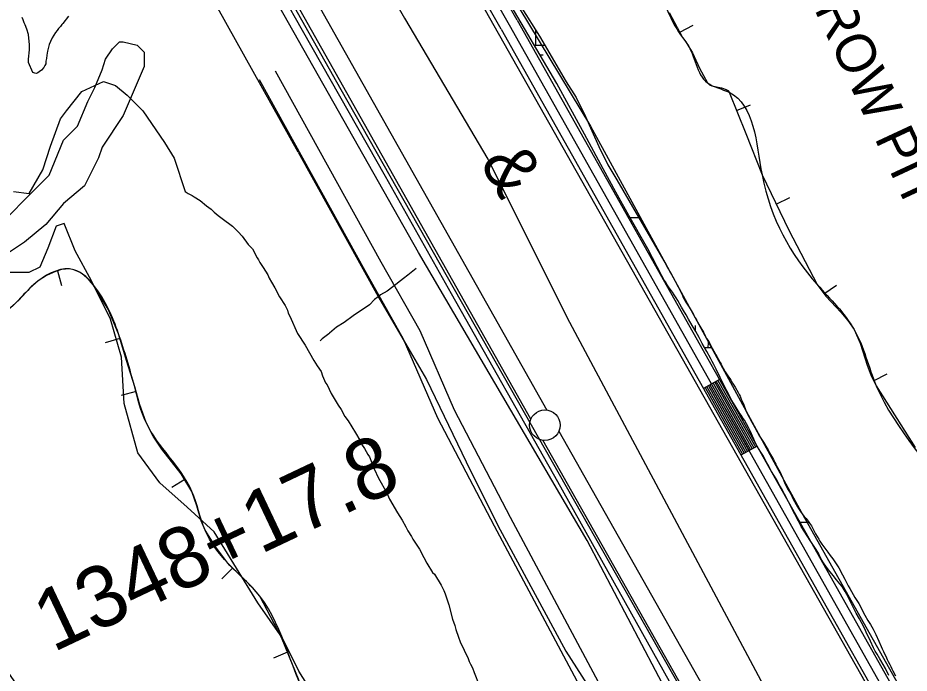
# Model space of a CAD drawing. Extents: x 3177185 to 3215018, y 812988 to 838321.
# Drawn here: x 3193125 to 3194584, y 822130 to 823203 of the extents above; entities that cross this region are included whole.
import ezdxf

# ---------------------------------------------------------------- set-up
doc = ezdxf.new("R2010")
doc.units = 0
for name, color, linetype in [('V-BORW-IDEN', 7, 'Continuous'), ('V-BORW-LINE', 7, 'Continuous'), ('V-LEVE-TOET', 7, 'Continuous'), ('V-RAIL-IDEN', 7, 'Continuous'), ('V-RAIL-TRAK', 7, 'Continuous'), ('V-ROAD-CNTR', 7, 'Continuous'), ('V-SITE-VEGE', 7, 'Continuous'), ('V-SURV-IDEN', 7, 'Continuous'), ('V-SURV-LINE', 7, 'Continuous'), ('V-TOPO-SHOR', 7, 'Continuous'), ('V-WETL-SWMP', 7, 'Continuous')]:
    doc.layers.add(name, color=color, linetype=linetype)

msp = doc.modelspace()

# ---------------------------------------------------------------- linework, layer by layer
at = {"layer": 'V-BORW-LINE'}
for p, q in [((3194208.7, 823179.2), (3194230.8, 823191)), ((3194301.5, 823051.1), (3194324.6, 823060.5)), ((3194366.5, 822897.8), (3194389, 822908.7)), ((3193190.1, 822788.7), (3193197.1, 822764.7)), ((3194444.7, 822750.9), (3194465.1, 822765.5)), ((3193292.5, 822678.2), (3193268.6, 822671)), ((3194526, 822608.6), (3194548.3, 822620)), ((3193318.9, 822591.2), (3193294.8, 822584.6)), ((3193398.5, 822446.9), (3193377.2, 822433.8)), ((3193477, 822302.2), (3193459.5, 822284.4)), ((3193566.8, 822164.2), (3193543.6, 822154.7))]:
    msp.add_line(p, q, dxfattribs=at)
for points in [[(3194191.4, 823211.7), (3194213.4, 823170.5), (3194216.8, 823165.7), (3194220.4, 823161), (3194229.5, 823145.4), (3194241, 823120.5), (3194253.9, 823096.6), (3194257.2, 823093.3), (3194261, 823091.5), (3194277.1, 823088.2), (3194284.4, 823085.8), (3194287.2, 823083.8), (3194289.3, 823081), (3194316.7, 823013.5), (3194343.3, 822945.9), (3194387, 822855.3), (3194433.8, 822766.2), (3194447.6, 822747), (3194472.2, 822720.8), (3194483.9, 822707.4), (3194494, 822692.8), (3194504.1, 822670.2), (3194515.4, 822634.3), (3194521.8, 822616.7), (3194530.3, 822600.2), (3194593.9, 822499.3)], [(3193316.9, 822598.6), (3193303.4, 822642.1), (3193290.2, 822685.8), (3193273, 822726.2), (3193249.5, 822765), (3193242.6, 822773.6), (3193236.8, 822779.3), (3193227.3, 822786.2), (3193217.2, 822790.6), (3193210.2, 822791.8), (3193197.1, 822790.7), (3193187.1, 822787.8), (3193172.2, 822780.9), (3193158.6, 822772.1), (3193145, 822760.2), (3193126.8, 822740.6), (3193107.6, 822723.1)], [(3193585.9, 822117.5), (3193556.8, 822188.5), (3193521.5, 822255.9), (3193509.5, 822270.3), (3193469.1, 822310), (3193449.3, 822336.3), (3193431.9, 822364.3), (3193425.4, 822379.7), (3193418.6, 822404.1), (3193410.3, 822427.7), (3193392.6, 822456.4), (3193361.3, 822497), (3193346.8, 822518), (3193335.2, 822540.6), (3193324.9, 822569.2), (3193316.9, 822598.6)]]:
    msp.add_lwpolyline(points, dxfattribs=at)
for points in [[(3194173.2, 823254.5), (3194133.8, 823323.1), (3194017.5, 823523.4), (3193991.8, 823555.6), (3193946.2, 823648.6), (3193888.3, 823652.4), (3193891.4, 823658.1), (3193914.7, 823669.6), (3193993, 823701.8), (3194039.3, 823727.5), (3194160.2, 823798.2), (3194326.1, 823907.6), (3194436.7, 823987.3), (3194502.9, 824036.7), (3194535.5, 824045.1), (3194547.6, 824055.8), (3194568.2, 824150.6), (3194657.5, 824394.2), (3194690.3, 824441.2), (3194711.1, 824446.4), (3194734.7, 824446.4), (3194770.2, 824392.5), (3194839.9, 824358.9), (3194843.7, 824354.2), (3194822.9, 824352.6), (3194805.6, 824354.5), (3194783.8, 824344), (3194808, 824310.6), (3194860.9, 824111.5), (3194890.3, 824049), (3194919.9, 824022.8), (3194936.8, 823993.7), (3194967.5, 823945.1), (3194990.2, 823878.8), (3195044.4, 823786.8), (3195063.9, 823718), (3195053.2, 823688.8), (3195056.3, 823616.2), (3195008.6, 823396.2), (3194962.2, 823257.3), (3194949.6, 823254.7), (3194916.1, 823270.5), (3194892.6, 823394.4), (3194818.7, 823675.4), (3194764.8, 823725), (3194732.1, 823768.5), (3194627.7, 823861.2), (3194598.2, 823922.8), (3194572.9, 824011.1), (3194544.8, 824024.5), (3194532.2, 824018.4), (3194535.7, 823972.4), (3194544.3, 823935.6), (3194590.6, 823765.3), (3194640.4, 823657.8), (3194680.8, 823529.9), (3194719.1, 823459), (3194750.6, 823333.9), (3194793.9, 823142.5), (3194772.9, 823135.8), (3194752.4, 823099.7), (3194748.5, 823050.4), (3194776.1, 822932.3), (3194811.1, 822874.8), (3194830.8, 822797.1), (3194831.1, 822768.9), (3194796.7, 822656), (3194757.4, 822452), (3194745.4, 822448.1), (3194718.1, 822363.5), (3194698.9, 822349.8), (3194685.3, 822355.9), (3194657.8, 822398.5), (3194530.3, 822600.2), (3194494, 822692.8), (3194433.8, 822766.2), (3194343.3, 822945.9), (3194289.3, 823081), (3194253.9, 823096.6), (3194220.4, 823161), (3194213.4, 823170.5), (3194173.2, 823254.5)], [(3193316.9, 822598.6), (3193335.2, 822540.6), (3193410.3, 822427.7), (3193431.9, 822364.3), (3193469.1, 822310), (3193521.5, 822255.9), (3193609.2, 822072.6), (3193646.8, 822019.2), (3193676.9, 821957.1), (3193720.8, 821903.1), (3193750, 821838.8), (3193830.2, 821730.3), (3193879.7, 821614.9), (3193980.5, 821434.8), (3194001.3, 821375.3), (3194045.6, 821322.9), (3194255.4, 820971.9), (3194278.3, 820910.6), (3194299.8, 820853), (3194335.6, 820798.4), (3194443.8, 820680.4), (3194483.4, 820494.4), (3194474.8, 820430), (3194362.4, 820338.7), (3194243.4, 820273.7), (3194115.5, 820232.8), (3193985.1, 820192.2), (3193871, 820096.9), (3193700.8, 819982), (3193642.2, 819950.8), (3193574.5, 819997.4), (3193482.7, 820109.4), (3193411.4, 820226.4), (3193461, 820288.3), (3193516, 820325.3), (3193569.4, 820370.5), (3193689.7, 820437.3), (3193809.3, 820477.2), (3193921.8, 820552.8), (3193973.7, 820602), (3193968.2, 820665.5), (3193943.7, 820740.3), (3193889.6, 820861.5), (3193818.7, 820974.4), (3193871.9, 821026.9), (3193893.2, 821093.5), (3193831.6, 821288.3), (3193762, 821415.9), (3193682.1, 821525.7), (3193580.7, 821633.2), (3193582.1, 821571.4), (3193675.7, 821399.4), (3193689.4, 821337.7), (3193683, 821270), (3193666, 821201.1), (3193594.8, 821238.9), (3193552.5, 821298.8), (3193499, 821351.2), (3193535.6, 821424), (3193485.3, 821613.1), (3193426.4, 821662.5), (3193356.9, 821777.8), (3193308.4, 821900.5), (3193294.3, 821963), (3193279.7, 822022.1), (3193265.1, 822081.6), (3193249.6, 822013.9), (3193262.2, 821951.7), (3193210.3, 822002.4), (3193038.4, 822236.4), (3192901.1, 822477.4), (3192892.6, 822538.2), (3192940.3, 822603.2), (3192988.9, 822662), (3193107.6, 822723.1), (3193158.6, 822772.1), (3193217.2, 822790.6), (3193249.5, 822765), (3193290.2, 822685.8), (3193316.9, 822598.6)]]:
    msp.add_spline(points, degree=3, dxfattribs=at)
at = {"layer": 'V-LEVE-TOET'}
for points in [[(3193506.6, 823644.9), (3193758.4, 823202.4), (3193894.5, 822971.4)], [(3193584.3, 822982.9), (3193407.8, 823299.3)], [(3193584.3, 822982.9), (3193715.2, 822746.5), (3193715.3, 822746.3)], [(3193894.5, 822971.4), (3194028.2, 822704.5), (3194448.5, 821917.6)], [(3193715.3, 822746.3), (3193717.9, 822741.8), (3193794.1, 822610.8), (3193858.9, 822476), (3193911.1, 822371.7), (3194022.5, 822165.9), (3194144.7, 821975), (3194195.9, 821891.8), (3194255.3, 821803.4)]]:
    msp.add_lwpolyline(points, dxfattribs=at)
at = {"layer": 'V-RAIL-TRAK'}
for points in [[(3193727.3, 822943), (3193577.7, 823206), (3193415.9, 823494.6), (3193219.9, 823842.7), (3193027.5, 824182.9), (3192797.1, 824592.3), (3192558.2, 825016.7), (3192352.2, 825381.7), (3192184.3, 825679.9), (3191974.4, 826050.6), (3191871.7, 826233.9)], [(3194238.4, 822033.7), (3194009.1, 822443.2), (3193835.4, 822751.2), (3193727.3, 822943)]]:
    msp.add_lwpolyline(points, dxfattribs=at)
at = {"layer": 'V-ROAD-CNTR'}
for p, q in [((3194273.8, 822610.8), (3194247.6, 822596)), ((3194335.1, 822501.8), (3194308.9, 822487.1))]:
    msp.add_line(p, q, dxfattribs=at)
for points in [[(3193916.6, 823184.2), (3193721.8, 823525.6), (3193306.3, 824253.5), (3192602.8, 825503.8), (3192579.7, 825544.8), (3192573, 825567.5), (3192571, 825597.1), (3192577.3, 825631.2), (3192615.1, 825721.3), (3192625.4, 825758.7), (3192631.4, 825785.7), (3192630.5, 825811.3), (3192625.4, 825832.9), (3192604.1, 825875.3), (3192381.8, 826278.2), (3192358.9, 826315.5), (3192335.4, 826340.9), (3192319.5, 826354.7), (3192289.4, 826371.6), (3192167.7, 826420.9)], [(3191892.3, 826207.1), (3193654.2, 823085.5)], [(3193942.6, 823199), (3193747.9, 823540.4), (3193728, 823575.3)], [(3193734.8, 823533), (3193929.6, 823191.6)], [(3193942.7, 823199), (3195097.4, 821147.5)], [(3193916.5, 823184.3), (3195071.3, 821132.7)], [(3193929.6, 823191.6), (3195084.4, 821140.1)], [(3193546.7, 823116.4), (3193719.6, 822803.7), (3193783.2, 822690.8), (3193839.5, 822561.1), (3193931.2, 822385.2), (3194075.1, 822116.1), (3194127.2, 822033.7), (3194185.2, 821977.8), (3194639.7, 821147.1), (3195029.5, 820446.4), (3195072.9, 820348.7), (3195192.1, 820158.7), (3195238.4, 820041.1), (3195343.7, 819857.8), (3195584.5, 819427.5), (3195690.6, 819249.8), (3195813.3, 819032.3), (3196001.4, 818698.6), (3196174.6, 818374.5)], [(3193520.4, 823101.8), (3193693.4, 822789.1), (3193756.3, 822677.4), (3193812.4, 822548.2), (3193904.7, 822371.2), (3194049.2, 822101), (3194103.8, 822014.6), (3194161.1, 821959.4), (3194613.5, 821132.6), (3195002.6, 820433), (3195046.3, 820334.6), (3195165.2, 820145.1), (3195211.3, 820028), (3195317.6, 819843), (3195558.5, 819412.5), (3195664.6, 819234.7), (3195787.2, 819017.6), (3195975.1, 818684.1), (3196148.1, 818360.4)], [(3193654.2, 823085.5), (3194393.6, 821781.9), (3194932.5, 820818.5), (3195643.8, 819559.4), (3196039.6, 818863.6), (3196103.7, 818747.1), (3196200.1, 818577.4), (3196283.3, 818430.9), (3196319.7, 818367.1)], [(3194271.1, 822609.3), (3194332.5, 822500.4)], [(3194250.2, 822597.5), (3194311.5, 822488.6)], [(3194252.8, 822599), (3194314.2, 822490.1)], [(3194255.5, 822600.5), (3194316.8, 822491.5)], [(3194258.1, 822601.9), (3194319.4, 822493)], [(3194260.7, 822603.4), (3194322, 822494.5)], [(3194263.3, 822604.9), (3194324.6, 822495.9)], [(3194265.9, 822606.3), (3194327.2, 822497.4)], [(3194268.5, 822607.8), (3194329.8, 822498.9)]]:
    msp.add_lwpolyline(points, dxfattribs=at)
at = {"layer": 'V-SITE-VEGE'}
for p, q in [((3193230.4, 823082.5), (3193265.7, 823098.5)), ((3193265.7, 823098.5), (3193285, 823092.1)), ((3193285, 823092.1), (3193304.3, 823076.1)), ((3193204.8, 823050.4), (3193230.4, 823082.5)), ((3193304.3, 823076.1), (3193329.9, 823050.4)), ((3193195.1, 823037.5), (3193204.8, 823050.4)), ((3193329.9, 823050.4), (3193365.2, 822999)), ((3193179.1, 822992.6), (3193195.1, 823037.5)), ((3193166.3, 822954.1), (3193179.1, 822992.6)), ((3193365.2, 822999), (3193381.3, 822973.3)), ((3193381.3, 822973.3), (3193399, 822918.7)), ((3193143.8, 822915.5), (3193166.3, 822954.1)), ((3193118.1, 822918.7), (3193143.8, 822915.5)), ((3193399, 822918.7), (3193404.4, 822915.5)), ((3193404.4, 822915.5), (3193410.7, 822912.2)), ((3193410.7, 822912.2), (3193413.8, 822909.8)), ((3193413.8, 822909.8), (3193423.9, 822904.1)), ((3193423.9, 822904.1), (3193434, 822895.2)), ((3193434, 822895.2), (3193441.8, 822889.6)), ((3193441.8, 822889.6), (3193446.5, 822884.8)), ((3193446.5, 822884.8), (3193453.5, 822879.1)), ((3193453.5, 822879.1), (3193459.7, 822874.3)), ((3193459.7, 822874.3), (3193476.8, 822862.1)), ((3193188, 822861.7), (3193174.6, 822826)), ((3193201.4, 822866.2), (3193188, 822861.7)), ((3193219.3, 822821.5), (3193201.4, 822866.2)), ((3193476.8, 822862.1), (3193486.1, 822852.5)), ((3193486.1, 822852.5), (3193492.3, 822845.3)), ((3193492.3, 822845.3), (3193502.3, 822831.7)), ((3193502.3, 822831.7), (3193509.3, 822824.5)), ((3193174.6, 822826), (3193161.2, 822794.7)), ((3193246.1, 822772.4), (3193219.3, 822821.5)), ((3193509.3, 822824.5), (3193516.9, 822810.1)), ((3193516.9, 822810.1), (3193519.2, 822806.9)), ((3193519.2, 822806.9), (3193521.5, 822802.2)), ((3193521.5, 822802.2), (3193526.9, 822794.2)), ((3193143.4, 822785.8), (3193107.6, 822785.8)), ((3193161.2, 822794.7), (3193143.4, 822785.8)), ((3193526.9, 822794.2), (3193534.5, 822782.2)), ((3193277.3, 822709.8), (3193246.1, 822772.4)), ((3193534.5, 822782.2), (3193536.8, 822776.7)), ((3193536.8, 822776.7), (3193540.6, 822770.3)), ((3193540.6, 822770.3), (3193546, 822760.7)), ((3193546, 822760.7), (3193553.6, 822746.4)), ((3193553.6, 822746.4), (3193562.8, 822732)), ((3193562.8, 822732), (3193566.6, 822724.1)), ((3193566.6, 822724.1), (3193568.1, 822719.3)), ((3193568.1, 822719.3), (3193570.4, 822714.5)), ((3193570.4, 822714.5), (3193583.3, 822685.9)), ((3193295.2, 822647.3), (3193277.3, 822709.8)), ((3193583.3, 822685.9), (3193595.6, 822666.8)), ((3193595.6, 822666.8), (3193610.1, 822642.1)), ((3193299.6, 822571.3), (3193295.2, 822647.3)), ((3193610.1, 822642.1), (3193615.5, 822633.3)), ((3193615.5, 822633.3), (3193621.6, 822623.7)), ((3193621.6, 822623.7), (3193623.9, 822616.6)), ((3193623.9, 822616.6), (3193629.2, 822605.5)), ((3193629.2, 822605.5), (3193631.5, 822602.3)), ((3193631.5, 822602.3), (3193638.3, 822587.9)), ((3193638.3, 822587.9), (3193649.8, 822568.8)), ((3193322, 822490.9), (3193299.6, 822571.3)), ((3193649.8, 822568.8), (3193654.4, 822561.6)), ((3193654.4, 822561.6), (3193660.5, 822550.5)), ((3193660.5, 822550.5), (3193665.9, 822543.3)), ((3193665.9, 822543.3), (3193678.2, 822523.3)), ((3193678.2, 822523.3), (3193685.1, 822511.4)), ((3193685.1, 822511.4), (3193688.1, 822505)), ((3193688.1, 822505), (3193692.7, 822497.8)), ((3193692.7, 822497.8), (3193698.1, 822488.3)), ((3193357.7, 822441.8), (3193322, 822490.9)), ((3193698.1, 822488.3), (3193701.1, 822484.3)), ((3193701.1, 822484.3), (3193708.7, 822464.4)), ((3193708.7, 822464.4), (3193715.5, 822449.3)), ((3193715.5, 822449.3), (3193729.3, 822425.4)), ((3193402.3, 822401.6), (3193357.7, 822441.8)), ((3193729.3, 822425.4), (3193733.8, 822415.1)), ((3193733.8, 822415.1), (3193746.8, 822392.8)), ((3193447, 822361.3), (3193402.3, 822401.6)), ((3193746.8, 822392.8), (3193754.5, 822380.8)), ((3193754.5, 822380.8), (3193760.6, 822369.7)), ((3193496.1, 822280.9), (3193447, 822361.3)), ((3193760.6, 822369.7), (3193763.6, 822363.3)), ((3193763.6, 822363.3), (3193769.8, 822353.7)), ((3193769.8, 822353.7), (3193772.1, 822349.7)), ((3193772.1, 822349.7), (3193782.8, 822333)), ((3193782.8, 822333), (3193789.7, 822319.4)), ((3193789.7, 822319.4), (3193795, 822309.9)), ((3193795, 822309.9), (3193804.2, 822294.7)), ((3193804.2, 822294.7), (3193807.3, 822292.3)), ((3193807.3, 822292.3), (3193818, 822274)), ((3193518.4, 822245.2), (3193496.1, 822280.9)), ((3193818, 822274), (3193822.6, 822265.2)), ((3193822.6, 822265.2), (3193824.9, 822259.7)), ((3193824.9, 822259.7), (3193830.9, 822242.2)), ((3193558.6, 822187.1), (3193518.4, 822245.2)), ((3193830.9, 822242.2), (3193836.8, 822218.4)), ((3193836.8, 822218.4), (3193840.5, 822208.1)), ((3193840.5, 822208.1), (3193842, 822201.8)), ((3193842, 822201.8), (3193846.5, 822189.1)), ((3193585.4, 822133.5), (3193558.6, 822187.1)), ((3193846.5, 822189.1), (3193849.5, 822181.2)), ((3193849.5, 822181.2), (3193862.4, 822154.1)), ((3193862.4, 822154.1), (3193863.9, 822149.3)), ((3193863.9, 822149.3), (3193866.2, 822144.6)), ((3193866.2, 822144.6), (3193869.3, 822139)), ((3193616.7, 822084.4), (3193585.4, 822133.5)), ((3193869.3, 822139), (3193872.3, 822131.1)), ((3193872.3, 822131.1), (3193880.6, 822110.4))]:
    msp.add_line(p, q, dxfattribs=at)
msp.add_lwpolyline([(3193208.4, 823205.9), (3193199.1, 823193.7), (3193197.4, 823192.1), (3193195, 823188.5), (3193192.2, 823185.7), (3193189.7, 823182), (3193186.9, 823178.8), (3193181.6, 823169.9), (3193178.8, 823164.2), (3193176.7, 823159.4), (3193175.1, 823152.5), (3193173.9, 823148.1), (3193173.1, 823141.6), (3193172.6, 823136.3), (3193171.4, 823131.9), (3193171, 823127.8), (3193169.8, 823124.6), (3193168.2, 823121.4), (3193164.1, 823117.3), (3193160.1, 823114.5), (3193158, 823112.9), (3193156, 823111.7), (3193153.2, 823112.1), (3193149.9, 823113.3), (3193143.1, 823129.9), (3193143.1, 823135.2), (3193144.3, 823150.5), (3193144.4, 823159.4), (3193144, 823164.3), (3193142.8, 823175.6), (3193140.4, 823184.5), (3193137.5, 823191.4), (3193135.9, 823194.7), (3193133.9, 823199.5), (3193132.7, 823203.2)], dxfattribs=at)
at = {"layer": 'V-SURV-LINE'}
for points in [[(3192530.9, 825151.2), (3193991.3, 822560.8)], [(3193965.1, 822546.1), (3192504.7, 825136.5)], [(3194010.9, 822526.1), (3195297.4, 820248.2)], [(3195271.3, 820233.4), (3193984.8, 822511.3)]]:
    msp.add_lwpolyline(points, dxfattribs=at)
msp.add_circle((3193988, 822536.1), 25, dxfattribs=at)
at = {"layer": 'V-TOPO-SHOR'}
for points in [[(3195564, 819660.7), (3195052.1, 820581.1), (3194839.3, 820937.7), (3194281, 821921.4), (3194057, 822347), (3193780.9, 822818.6), (3193257.4, 823744.7), (3192803, 824538.5), (3192509.7, 825084.9), (3192365.9, 825332.3), (3191974.7, 826039.8)], [(3192480.9, 825591.1), (3192521.2, 825596.9), (3192561.4, 825596.9), (3192590.2, 825510.6), (3193027.4, 824751.3), (3193700.3, 823554.9), (3193890.2, 823215.5), (3194810.5, 821587.7), (3194919.8, 821386.4), (3195149.9, 820978), (3195149.9, 820885.9), (3195144.1, 820851.4), (3195103.9, 820788.1), (3195086.6, 820747.9)], [(3193915.7, 823672.7), (3193769.4, 823583.6), (3193763.6, 823554.9), (3193780.9, 823520.4), (3193821.1, 823445.6), (3193849.9, 823445.6), (3193849.9, 823445.6), (3193861.4, 823428.3), (3193849.9, 823411.1), (3193849.9, 823405.3), (3193861.4, 823359.3), (3194062.7, 823025.7), (3194407.9, 822393), (3195055.4, 821242.2)], [(3193107.9, 822876.1), (3193142.4, 822910.7), (3193176.9, 822945.2), (3193199.9, 823002.7), (3193222.9, 823025.7), (3193240.2, 823066), (3193251.7, 823089), (3193263.2, 823117.7), (3193268.9, 823135), (3193280.4, 823152.2), (3193292, 823163.7), (3193297.7, 823163.7), (3193320.7, 823158), (3193332.2, 823146.5), (3193332.2, 823123.5), (3193297.7, 823043), (3193263.2, 822991.2), (3193257.4, 822973.9), (3193234.4, 822927.9), (3193199.9, 822899.2), (3193171.2, 822864.6), (3193136.6, 822835.9), (3193102.1, 822812.9)], [(3193777.1, 822792.3), (3193763.5, 822781.6), (3193756.6, 822776.2), (3193739.3, 822762.6), (3193729.7, 822755.4), (3193719.1, 822749.2), (3193715.3, 822746.3)], [(3193715.3, 822746.3), (3193709.3, 822741.7), (3193700.8, 822733.2), (3193674.2, 822715.1), (3193659.5, 822704.4), (3193647.1, 822696.3), (3193635.7, 822686.9), (3193634.3, 822685.6), (3193623.6, 822677.4), (3193620.1, 822674.2)]]:
    msp.add_lwpolyline(points, dxfattribs=at)
at = {"layer": 'V-WETL-SWMP'}
for p, q in [((3193973.3, 823157.9), (3193973.3, 823182.3)), ((3193970.6, 823157.9), (3193988, 823157.9)), ((3193979.7, 823142.4), (3193985.3, 823142.4)), ((3194127.8, 822875.9), (3194141.8, 822875.9)), ((3194234.7, 822690.3), (3194234.7, 822699.3)), ((3194249.2, 822663.3), (3194261, 822663.3)), ((3194403.6, 822377.1), (3194420.2, 822377.1))]:
    msp.add_line(p, q, dxfattribs=at)
for points in [[(3194125.3, 822879.3), (3194104.3, 822917.4), (3194083.4, 822955.8), (3194053, 823012.4), (3194007.3, 823095.6), (3193927.1, 823231.6)], [(3193950, 823218.5), (3193979.2, 823173.1), (3194022.7, 823098), (3194038.9, 823072.6), (3194054.6, 823041.5), (3194064.7, 823018.1), (3194076, 822992.3), (3194091.2, 822962.3), (3194105.9, 822937.6), (3194186.7, 822798.7), (3194188.3, 822794.9), (3194190, 822791.2), (3194192.6, 822787.1), (3194194.7, 822783.9), (3194197.5, 822778.8), (3194199.9, 822774.2), (3194202.2, 822769.8), (3194204.1, 822766.1), (3194206.2, 822762.4), (3194211, 822753.2), (3194212.9, 822748.1), (3194214.3, 822744.9), (3194215.7, 822742.2), (3194217.3, 822738.9), (3194221.8, 822732.7), (3194224.2, 822729.3), (3194225.8, 822726.5), (3194227.2, 822723.7), (3194231, 822717.1), (3194233.8, 822711.8), (3194235.9, 822708.5), (3194237.6, 822704.8), (3194241.8, 822698.2), (3194247.5, 822688.3), (3194250.6, 822681.1), (3194252.7, 822678.1), (3194256, 822673), (3194258.5, 822668.2), (3194261.6, 822662), (3194264.2, 822657.4), (3194267.7, 822651.4), (3194269.4, 822648.4), (3194274.6, 822638.7), (3194276.2, 822635.9), (3194277.4, 822633.2), (3194279.8, 822629.3), (3194283.1, 822623.3), (3194288.7, 822615.2), (3194290.6, 822612.5), (3194292.5, 822609.5), (3194295.1, 822604.9), (3194299.5, 822598), (3194304.2, 822589.7), (3194305.9, 822586.2), (3194307.3, 822583.4), (3194309.2, 822578.8), (3194310.6, 822575.1), (3194313.5, 822569.1), (3194317, 822560.1), (3194320.3, 822553), (3194322, 822549.3), (3194324.1, 822545.8), (3194326.5, 822541), (3194331.4, 822532), (3194333.8, 822528.1), (3194335.4, 822525.3), (3194337.8, 822521), (3194339.4, 822518), (3194345.8, 822508.5), (3194347.4, 822505.5), (3194351.2, 822499.1), (3194353.1, 822495.8), (3194355.7, 822491), (3194360.4, 822482.7)], [(3194550.9, 822126.2), (3194545.2, 822137.7), (3194537.7, 822150.6), (3194536, 822153.4), (3194531.6, 822161.2), (3194528.7, 822166.3), (3194525.9, 822171.4), (3194520.7, 822182.2), (3194513.9, 822197), (3194512.4, 822200), (3194508.7, 822208), (3194506.3, 822212.9), (3194502.8, 822218.9), (3194497.3, 822228.5), (3194491.4, 822240.1), (3194487.2, 822249), (3194485.3, 822253), (3194482, 822259), (3194479.2, 822264), (3194474.2, 822271.9), (3194470.7, 822276.5), (3194465.1, 822282.9), (3194459.5, 822290), (3194452.2, 822299), (3194447.5, 822305), (3194443.8, 822310.9), (3194441.4, 822314.9), (3194438.6, 822319.9), (3194435.5, 822326.6), (3194430.6, 822334.4), (3194422.1, 822347.1), (3194407.3, 822370.1), (3194402.8, 822378.7), (3194396.9, 822390.2), (3194393.8, 822396.6), (3194389.1, 822404.9), (3194386.8, 822410.5), (3194381.3, 822421.3), (3194378.7, 822426.1), (3194376.1, 822430.7), (3194372.6, 822437), (3194370.3, 822441.3), (3194366.3, 822448), (3194358.7, 822460.2), (3194352.6, 822471.5), (3194351.2, 822474.3), (3194348.3, 822479.8), (3194344.6, 822487), (3194341.5, 822492), (3194336.1, 822500.6), (3194332.3, 822507.7), (3194330, 822513.2), (3194327.6, 822518.3), (3194324.3, 822525.7), (3194321.2, 822532.4), (3194314.4, 822544.4), (3194312.3, 822547.1), (3194309.4, 822552.2), (3194307.1, 822554.9), (3194301.2, 822564.8), (3194293.9, 822576.6), (3194291.8, 822580.7), (3194285.7, 822592.5), (3194283.5, 822596.4), (3194280.2, 822603.3), (3194275, 822613.9), (3194268.4, 822628), (3194264.2, 822635.4), (3194261.8, 822640.4), (3194259, 822645.7), (3194252.9, 822656.6), (3194245.6, 822669.9), (3194242.7, 822675), (3194240.4, 822679.6), (3194237.8, 822684.7), (3194235.2, 822689.5), (3194229.1, 822699.4), (3194223.2, 822709.6), (3194218.9, 822716.7), (3194214.7, 822723.6), (3194211.6, 822729.1), (3194205.5, 822740.2), (3194202.9, 822744.6), (3194199.4, 822749.6), (3194196.6, 822753.6), (3194193.3, 822758.2), (3194191.4, 822760.9), (3194187.2, 822767.4), (3194185.8, 822770.1), (3194183.4, 822773.6), (3194179.9, 822780), (3194179.4, 822780.3), (3194156.6, 822824.8), (3194125.3, 822879.3)], [(3194360.4, 822482.7), (3194362.2, 822479.7), (3194364.4, 822475.1), (3194366, 822472.3), (3194368.9, 822466.6), (3194372.9, 822459), (3194374.5, 822455.1), (3194377.1, 822449.1), (3194380, 822442.1), (3194382.3, 822437.3), (3194384.9, 822431.8), (3194388.5, 822426.7), (3194390.3, 822423), (3194392, 822419.8), (3194393.4, 822417), (3194396.5, 822411), (3194399.3, 822406), (3194401.4, 822402.3), (3194403.1, 822399.7), (3194407.5, 822393.1), (3194410.4, 822388.9), (3194412.5, 822386.4), (3194415.5, 822383.2), (3194418.8, 822379), (3194421.1, 822375.8), (3194424.2, 822371), (3194427.3, 822364.8), (3194431, 822358.1), (3194436.2, 822349.3), (3194437.9, 822346.3), (3194441.1, 822341.5), (3194446.1, 822334.8), (3194451, 822328.2), (3194454.8, 822322.9), (3194459, 822317.1), (3194462.3, 822312.5), (3194468.8, 822302.6), (3194475.2, 822291.1), (3194478.7, 822284.2), (3194480.9, 822279.8), (3194484.4, 822272.9), (3194487, 822268.5), (3194495.2, 822254), (3194498.3, 822248.9), (3194501.6, 822243.9), (3194505.6, 822236.9), (3194507.7, 822232.1), (3194511.3, 822225.2), (3194516.4, 822216.4), (3194520.9, 822210), (3194523, 822205.8), (3194525.2, 822201.9), (3194527.7, 822196.9), (3194529.6, 822193.4), (3194534.6, 822182.3), (3194538.2, 822173.6), (3194539.8, 822169.9), (3194541.9, 822165.3), (3194546.9, 822155.1), (3194548.3, 822152.3), (3194550, 822148.9), (3194552.3, 822144), (3194554.2, 822141.1), (3194555.6, 822136.9), (3194557.3, 822134.1), (3194561.8, 822125.6)]]:
    msp.add_lwpolyline(points, dxfattribs=at)
msp.add_arc((3194289.9, 822663.8), 35.2, 164.7209, 180.7718, dxfattribs=at)

# ---------------------------------------------------------------- texts
at = {"layer": 'V-BORW-IDEN'}
msp.add_text('BORROW PIT', height=64, rotation=295, dxfattribs=at).set_placement((3194349.8, 823385.7))
at = {"layer": 'V-RAIL-IDEN'}
msp.add_text('&', height=83, rotation=300.2881, dxfattribs=at).set_placement((3193880.4, 822966.3))
at = {"layer": 'V-SURV-IDEN'}
msp.add_text('1348+17.8', height=100, rotation=25.35, dxfattribs=at).set_placement((3193182.9, 822163.4))

doc.saveas('drawing.dxf')
